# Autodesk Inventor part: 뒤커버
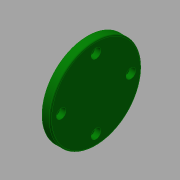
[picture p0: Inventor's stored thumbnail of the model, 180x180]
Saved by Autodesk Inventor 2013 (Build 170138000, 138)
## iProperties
Created: 2015-09
Part Number: 뒤커버
Material: 알루미늄 6061
Document SubType Name: Modeling
Designer: mduedu
Density: 2.71 g/cm^3
Mass: 54.0417 g
Surface Area: 84.9688 cm^2
Volume: 19.9416 cm^3
Author: mduedu
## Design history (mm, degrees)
sketch "스케치1"
  geometry: L1 (-15.5, 47)-(-15.5, 85); L2 (-15.5, 85)-(-22.5, 85); L3 (-22.5, 85)-(-22.5, 67); L4 (-25.5, 67)-(-25.5, 47); L5 (-79.5, 39.5)-(-79.5, 54.5) reference; L6 (48.5, 54.5)-(48.5, 39.5) reference; L7 (-79.5, 47)-(48.5, 47); L8 (-22.5, 67)-(-25.5, 67); L9 (-25.5, 47)-(-15.5, 47); 1 further point
  constraints: 14 end point, 4 midpoint, 3 parallel, 1 collinear, 1 point on line, 1 vertical
  dimensions: "d6" = 76 diameter of L2 L7; "d7" = 7 distance of L1.end L2.end; "d8" = 40 diameter of L3.end L7; "d32" = 10 distance between parallel lines of L1 L4
revolve "회전1" sketch "스케치1" stored, may be unused: angle "d4" = 90 deg
sketch "스케치4"
  geometry: C1 r 38 at (0, 0) reference; 2 further points
  constraints: 1 coincident
hole "구멍3" sketch "스케치4" at (0, 0) diameter "d33" = 33; stored, may be unused: countersink angle "d37" = 90 deg, drill point angle "d39" = 0 deg; dims "d34" = 6, "d35" = 4, "d36" = 2, "d38" = 5
fillet "모깎기4" dims "d40" = 1
chamfer "모따기2" distance "d41" = 1; stored, may be unused: second distance "d42" = 2, angle "d43" = 45 deg
sketch "스케치6" dims "d56" = 58
  geometry: C1 r 38 at (0, 0) reference; 5 further points
  constraints: 2 vertical alignment, 1 coincident, 7 other
  dimensions: "d59" = 360 deg dimension on C1.centre point (0, 29) (derived)
sketch "스케치7"
  geometry: 4 further points
  constraints: 4 other
hole "구멍5" sketch "스케치7" at (0, 29), (-29, 0), (29, 0), (0, -29) diameter "d62" = 4.5; stored, may be unused: countersink angle "d66" = 90 deg, drill point angle "d68" = 0 deg; dims "d63" = 6, "d64" = 8, "d65" = 4.6, "d67" = 8
node "솔리드1"
node "참조1"
node "참조2"
